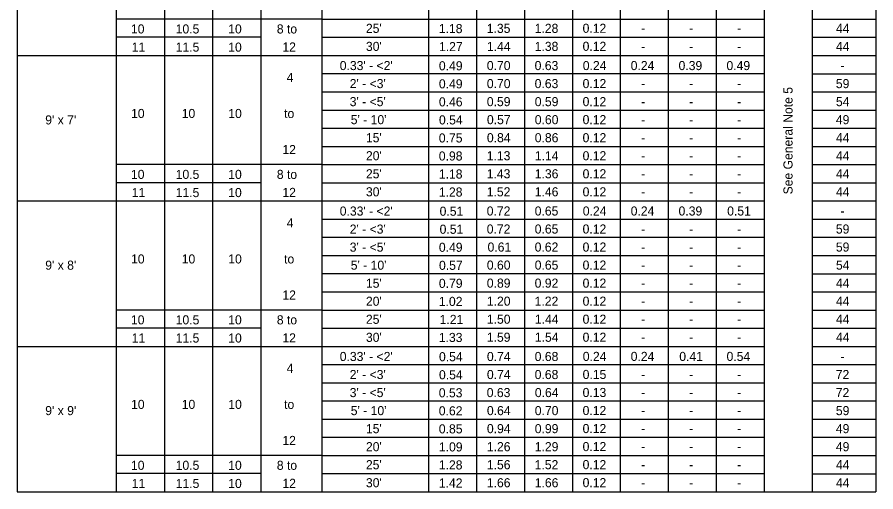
# Model space of a CAD drawing. Extents: x 10346.98 to 10349.19, y 76371.36 to 76372.62.
# Drawn here: x 10347.625 to 10348.22, y 76371.961 to 76372.289 of the extents above; entities that cross this region are included whole.
import ezdxf

# ---------------------------------------------------------------- set-up
doc = ezdxf.new("R2010")
doc.units = 0
doc.layers.add('AdhocPoint_dp', color=7, linetype='Continuous')
doc.layers.add('PlotBorder_dp', color=7, linetype='Continuous')

msp = doc.modelspace()

# ---------------------------------------------------------------- linework, layer by layer
at = {"layer": 'PlotBorder_dp'}
for p, q in [((10347.62504, 76372.53475), (10347.62504, 76371.96053)), ((10348.21977, 76372.53475), (10348.21977, 76371.96053)), ((10347.69367, 76372.51488), (10347.69367, 76371.96053)), ((10347.83612, 76372.51488), (10347.83612, 76371.96053)), ((10347.91, 76372.51488), (10347.91, 76371.96053)), ((10348.17559, 76372.51488), (10348.17559, 76371.96053)), ((10347.72703, 76372.50228), (10347.72703, 76371.96053)), ((10347.76039, 76372.50228), (10347.76039, 76371.96053)), ((10347.79375, 76372.50228), (10347.79375, 76371.96053)), ((10347.9432, 76372.47713), (10347.9432, 76371.96053)), ((10347.97639, 76372.47713), (10347.97639, 76371.96053)), ((10348.00959, 76372.47713), (10348.00959, 76371.96053)), ((10348.04279, 76372.47713), (10348.04279, 76371.96053)), ((10348.07599, 76372.47713), (10348.07599, 76371.96053)), ((10348.07599, 76372.47713), (10348.07599, 76371.96053)), ((10348.10919, 76372.47713), (10348.10919, 76371.96053)), ((10348.14239, 76372.47713), (10348.14239, 76371.96053)), ((10347.83612, 76372.28813), (10347.69367, 76372.28813)), ((10347.83612, 76372.28813), (10348.14239, 76372.28813)), ((10348.17559, 76372.28811), (10348.21977, 76372.28811)), ((10347.79375, 76372.27553), (10347.69367, 76372.27553)), ((10347.83612, 76372.27553), (10348.14239, 76372.27553)), ((10348.17559, 76372.27551), (10348.21977, 76372.27551)), ((10347.62504, 76372.26293), (10348.14239, 76372.26293)), ((10347.83673, 76372.26291), (10347.9089, 76372.26291)), ((10348.17559, 76372.26291), (10348.21977, 76372.26291)), ((10347.83612, 76372.25033), (10348.14239, 76372.25033)), ((10348.17559, 76372.25031), (10348.21977, 76372.25031)), ((10347.83612, 76372.23773), (10348.14239, 76372.23773)), ((10348.17559, 76372.23771), (10348.21977, 76372.23771)), ((10347.83612, 76372.22513), (10348.14239, 76372.22513)), ((10348.17559, 76372.22511), (10348.21977, 76372.22511)), ((10347.83612, 76372.21253), (10348.14239, 76372.21253)), ((10348.17559, 76372.21251), (10348.21977, 76372.21251)), ((10347.83612, 76372.19993), (10348.14239, 76372.19993)), ((10348.17559, 76372.19991), (10348.21977, 76372.19991)), ((10347.83612, 76372.18733), (10347.69367, 76372.18733)), ((10347.83612, 76372.18733), (10348.14239, 76372.18733)), ((10348.17559, 76372.18731), (10348.21977, 76372.18731)), ((10347.79375, 76372.17473), (10347.69367, 76372.17473)), ((10347.83612, 76372.17473), (10348.14239, 76372.17473)), ((10348.17559, 76372.17471), (10348.21977, 76372.17471)), ((10347.62504, 76372.16213), (10348.14239, 76372.16213)), ((10347.83673, 76372.16211), (10347.9089, 76372.16211)), ((10347.83673, 76372.16211), (10347.9089, 76372.16211)), ((10348.17559, 76372.16211), (10348.21977, 76372.16211)), ((10347.83612, 76372.14953), (10348.14239, 76372.14953)), ((10348.17559, 76372.14951), (10348.21977, 76372.14951)), ((10347.83612, 76372.13693), (10348.14239, 76372.13693)), ((10348.17559, 76372.13691), (10348.21977, 76372.13691)), ((10347.83612, 76372.12433), (10348.14239, 76372.12433)), ((10348.17559, 76372.12431), (10348.21977, 76372.12431)), ((10347.83612, 76372.11173), (10348.14239, 76372.11173)), ((10348.17559, 76372.11171), (10348.21977, 76372.11171)), ((10347.83612, 76372.09913), (10348.14239, 76372.09913)), ((10348.17559, 76372.09911), (10348.21977, 76372.09911)), ((10347.83612, 76372.08653), (10347.69367, 76372.08653)), ((10347.83612, 76372.08653), (10348.14239, 76372.08653)), ((10348.17559, 76372.08651), (10348.21977, 76372.08651)), ((10347.79375, 76372.07393), (10347.69367, 76372.07393)), ((10347.83612, 76372.07393), (10348.14239, 76372.07393)), ((10348.17559, 76372.07391), (10348.21977, 76372.07391)), ((10347.62504, 76372.06133), (10348.14239, 76372.06133)), ((10347.83673, 76372.06131), (10347.9089, 76372.06131)), ((10347.83673, 76372.06131), (10347.9089, 76372.06131)), ((10347.83673, 76372.06131), (10347.9089, 76372.06131)), ((10348.17559, 76372.06131), (10348.21977, 76372.06131)), ((10347.83612, 76372.04873), (10348.14239, 76372.04873)), ((10348.17559, 76372.04871), (10348.21977, 76372.04871)), ((10347.83612, 76372.03613), (10348.14239, 76372.03613)), ((10348.17559, 76372.03611), (10348.21977, 76372.03611)), ((10347.83612, 76372.02353), (10348.14239, 76372.02353)), ((10348.17559, 76372.02351), (10348.21977, 76372.02351)), ((10347.83612, 76372.01093), (10348.14239, 76372.01093)), ((10348.17559, 76372.01091), (10348.21977, 76372.01091)), ((10347.83612, 76371.99833), (10348.14239, 76371.99833)), ((10348.17559, 76371.99831), (10348.21977, 76371.99831)), ((10347.83612, 76371.98573), (10347.69367, 76371.98573)), ((10347.83612, 76371.98573), (10348.14239, 76371.98573)), ((10348.17559, 76371.98571), (10348.21977, 76371.98571)), ((10347.79375, 76371.97313), (10347.69367, 76371.97313)), ((10347.83612, 76371.97313), (10348.14239, 76371.97313)), ((10348.17559, 76371.97311), (10348.21977, 76371.97311)), ((10347.62504, 76371.96053), (10348.21977, 76371.96053))]:
    msp.add_line(p, q, dxfattribs=at)

# ---------------------------------------------------------------- texts
at = {"layer": 'AdhocPoint_dp'}
for s, p in [('10', (10347.70384, 76372.27818)), ('10.5', (10347.73483, 76372.27818)), ('10', (10347.77122, 76372.27818)), ('8 to', (10347.80488, 76372.27818)), ('11', (10347.70435, 76372.26558)), ('11.5', (10347.73483, 76372.26558)), ('10', (10347.77122, 76372.26558)), ('12', (10347.80874, 76372.26568)), ('10', (10347.70384, 76372.17738)), ('10.5', (10347.73483, 76372.17738)), ('10', (10347.77122, 76372.17738)), ('8 to', (10347.80488, 76372.17738)), ('11', (10347.70435, 76372.16478)), ('11.5', (10347.73483, 76372.16478)), ('10', (10347.77122, 76372.16478)), ('12', (10347.80874, 76372.16488)), ('10', (10347.70384, 76372.07658)), ('10.5', (10347.73483, 76372.07658)), ('10', (10347.77122, 76372.07658)), ('8 to', (10347.80488, 76372.07658)), ('11', (10347.70435, 76372.06398)), ('11.5', (10347.73483, 76372.06398)), ('10', (10347.77122, 76372.06398)), ('12', (10347.80874, 76372.06408)), ('10', (10347.70384, 76371.97578)), ('10.5', (10347.73483, 76371.97578)), ('10', (10347.77122, 76371.97578)), ('8 to', (10347.80488, 76371.97578)), ('11', (10347.70435, 76371.96318)), ('11.5', (10347.73483, 76371.96318)), ('10', (10347.77122, 76371.96318)), ('12', (10347.80874, 76371.96328))]:
    msp.add_text(s, height=0.0063, dxfattribs=at).set_placement(p)
msp.add_text('See General Note 5', height=0.0063, rotation=90, dxfattribs=at).set_placement((10348.16209, 76372.16663))
at = {"layer": 'PlotBorder_dp'}
for s, p in [("25'", (10347.8666, 76372.27858)), ('1.18', (10347.91709, 76372.27842)), ('1.35', (10347.9503, 76372.27858)), ('1.28', (10347.98349, 76372.27858)), ('0.12', (10348.01668, 76372.27863)), ('-', (10348.05726, 76372.27863)), ('-', (10348.09047, 76372.27863)), ('-', (10348.12366, 76372.27863)), ('44', (10348.19216, 76372.27858)), ("30'", (10347.8666, 76372.26608)), ('1.27', (10347.91721, 76372.26592)), ('1.44', (10347.9504, 76372.26608)), ('1.38', (10347.98349, 76372.26608)), ('0.12', (10348.01668, 76372.26613)), ('-', (10348.05726, 76372.26613)), ('-', (10348.09047, 76372.26613)), ('-', (10348.12366, 76372.26613)), ('44', (10348.19216, 76372.26608)), ("0.33' - <2'", (10347.84847, 76372.2528)), ('0.49', (10347.91714, 76372.25264)), ('0.70', (10347.95035, 76372.2528)), ('0.63', (10347.98347, 76372.2528)), ('0.24', (10348.0168, 76372.2528)), ('0.24', (10348.04999, 76372.2528)), ('0.39', (10348.08314, 76372.2528)), ('0.49', (10348.11632, 76372.2528)), ('4', (10347.8117, 76372.24458)), ('-', (10348.19536, 76372.2528)), ("2' - <3'", (10347.85537, 76372.2403)), ('0.49', (10347.91714, 76372.24014)), ('0.70', (10347.95035, 76372.2403)), ('0.63', (10347.98347, 76372.2403)), ('0.12', (10348.01668, 76372.2403)), ('59', (10348.1921, 76372.2403)), ('-', (10348.05726, 76372.2403)), ('-', (10348.09047, 76372.2403)), ('-', (10348.12366, 76372.2403)), ("3' - <5'", (10347.85537, 76372.2278)), ('0.46', (10347.91714, 76372.22764)), ('0.59', (10347.95034, 76372.2278)), ('0.59', (10347.98354, 76372.2278)), ('0.12', (10348.01668, 76372.2278)), ('54', (10348.19216, 76372.2278)), ('-', (10348.05726, 76372.2278)), ('-', (10348.09047, 76372.2278)), ('-', (10348.12366, 76372.2278)), ("9' x 7'", (10347.64447, 76372.21514)), ('10', (10347.70392, 76372.21958)), ('10', (10347.73901, 76372.21958)), ('10', (10347.77125, 76372.21958)), ('to', (10347.80992, 76372.21958)), ("5' - 10'", (10347.85608, 76372.2153)), ('0.54', (10347.9172, 76372.21514)), ('0.57', (10347.95041, 76372.2153)), ('0.60', (10347.98355, 76372.2153)), ('0.12', (10348.01668, 76372.2153)), ('49', (10348.1921, 76372.2153)), ('-', (10348.05726, 76372.2153)), ('-', (10348.09047, 76372.2153)), ('-', (10348.12366, 76372.2153)), ("15'", (10347.8666, 76372.2028)), ('0.84', (10347.9504, 76372.2028)), ('0.86', (10347.98354, 76372.2028)), ('0.12', (10348.01668, 76372.2028)), ('44', (10348.19216, 76372.2028)), ('0.75', (10347.9171, 76372.20264)), ('-', (10348.05726, 76372.2028)), ('-', (10348.09047, 76372.2028)), ('-', (10348.12366, 76372.2028)), ('12', (10347.80874, 76372.19458)), ("20'", (10347.8666, 76372.1903)), ('0.98', (10347.91709, 76372.19014)), ('1.13', (10347.95027, 76372.1903)), ('1.14', (10347.9836, 76372.1903)), ('0.12', (10348.01668, 76372.1903)), ('-', (10348.05726, 76372.1903)), ('-', (10348.09047, 76372.1903)), ('-', (10348.12366, 76372.1903)), ('44', (10348.19216, 76372.1903)), ("25'", (10347.8666, 76372.1778)), ('1.18', (10347.91709, 76372.17764)), ('1.43', (10347.95027, 76372.1778)), ('1.36', (10347.98354, 76372.1778)), ('0.12', (10348.01668, 76372.1778)), ('-', (10348.05726, 76372.1778)), ('-', (10348.09047, 76372.1778)), ('-', (10348.12366, 76372.1778)), ('44', (10348.19216, 76372.1778)), ("30'", (10347.8666, 76372.1653)), ('1.28', (10347.91709, 76372.16514)), ('1.52', (10347.95027, 76372.1653)), ('1.46', (10347.98354, 76372.1653)), ('0.12', (10348.01668, 76372.1653)), ('-', (10348.05726, 76372.1653)), ('-', (10348.09047, 76372.1653)), ('-', (10348.12366, 76372.1653)), ('44', (10348.19216, 76372.1653)), ("0.33' - <2'", (10347.84847, 76372.15196)), ('0.51', (10347.91764, 76372.15186)), ('0.72', (10347.95027, 76372.15202)), ('0.65', (10347.9835, 76372.15202)), ('0.24', (10348.0168, 76372.15202)), ('0.24', (10348.04999, 76372.15202)), ('0.39', (10348.08314, 76372.15202)), ('0.51', (10348.11682, 76372.15202)), ('4', (10347.8117, 76372.14378)), ('-', (10348.19536, 76372.15202)), ("2' - <3'", (10347.85537, 76372.13946)), ('0.51', (10347.91764, 76372.13936)), ('0.72', (10347.95027, 76372.13952)), ('0.65', (10347.9835, 76372.13952)), ('0.12', (10348.01668, 76372.13952)), ('59', (10348.1921, 76372.13952)), ('-', (10348.05726, 76372.13952)), ('-', (10348.09047, 76372.13952)), ('-', (10348.12366, 76372.13952)), ("3' - <5'", (10347.85537, 76372.12696)), ('0.49', (10347.91714, 76372.12686)), ('0.61', (10347.95084, 76372.12702)), ('0.62', (10347.98347, 76372.12702)), ('0.12', (10348.01668, 76372.12702)), ('59', (10348.1921, 76372.12702)), ('-', (10348.05726, 76372.12702)), ('-', (10348.09047, 76372.12702)), ('-', (10348.12366, 76372.12702)), ("9' x 8'", (10347.64447, 76372.11446)), ('10', (10347.70392, 76372.11878)), ('10', (10347.73901, 76372.11878)), ('10', (10347.77125, 76372.11878)), ('to', (10347.80992, 76372.11878)), ("5' - 10'", (10347.85608, 76372.11446)), ('0.57', (10347.91721, 76372.11436)), ('0.60', (10347.95035, 76372.11452)), ('0.65', (10347.9835, 76372.11452)), ('0.12', (10348.01668, 76372.11452)), ('54', (10348.19216, 76372.11452)), ('-', (10348.05726, 76372.11452)), ('-', (10348.09047, 76372.11452)), ('-', (10348.12366, 76372.11452)), ("15'", (10347.8666, 76372.10196)), ('0.79', (10347.91714, 76372.10186)), ('0.89', (10347.95034, 76372.10202)), ('0.92', (10347.98347, 76372.10202)), ('0.12', (10348.01668, 76372.10202)), ('44', (10348.19216, 76372.10202)), ('-', (10348.05726, 76372.10202)), ('-', (10348.09047, 76372.10202)), ('-', (10348.12366, 76372.10202)), ('12', (10347.80874, 76372.09378)), ("20'", (10347.8666, 76372.08946)), ('1.02', (10347.91707, 76372.08936)), ('1.20', (10347.95035, 76372.08952)), ('1.22', (10347.98347, 76372.08952)), ('0.12', (10348.01668, 76372.08952)), ('-', (10348.05726, 76372.08952)), ('-', (10348.09047, 76372.08952)), ('-', (10348.12366, 76372.08952)), ('44', (10348.19216, 76372.08952)), ("25'", (10347.8666, 76372.07696)), ('1.21', (10347.91764, 76372.07686)), ('1.50', (10347.95035, 76372.07702)), ('1.44', (10347.9836, 76372.07702)), ('0.12', (10348.01668, 76372.07702)), ('-', (10348.05726, 76372.07702)), ('-', (10348.09047, 76372.07702)), ('-', (10348.12366, 76372.07702)), ('44', (10348.19216, 76372.07702)), ("30'", (10347.8666, 76372.06446)), ('1.33', (10347.91707, 76372.06436)), ('1.59', (10347.95034, 76372.06452)), ('1.54', (10347.9836, 76372.06452)), ('0.12', (10348.01668, 76372.06452)), ('-', (10348.05726, 76372.06452)), ('-', (10348.09047, 76372.06452)), ('-', (10348.12366, 76372.06452)), ('44', (10348.19216, 76372.06452)), ("0.33' - <2'", (10347.84847, 76372.05118)), ('0.54', (10347.9172, 76372.05103)), ('0.74', (10347.9504, 76372.05118)), ('0.68', (10347.98349, 76372.05118)), ('0.24', (10348.0168, 76372.05124)), ('0.24', (10348.04999, 76372.05124)), ('0.41', (10348.08364, 76372.05124)), ('0.54', (10348.11638, 76372.05124)), ('4', (10347.8117, 76372.04298)), ('-', (10348.19536, 76372.05118)), ("2' - <3'", (10347.85537, 76372.03868)), ('0.54', (10347.9172, 76372.03853)), ('0.74', (10347.9504, 76372.03868)), ('0.68', (10347.98349, 76372.03868)), ('0.15', (10348.01671, 76372.03874)), ('72', (10348.19203, 76372.03868)), ('-', (10348.05726, 76372.03874)), ('-', (10348.09047, 76372.03874)), ('-', (10348.12366, 76372.03874)), ("3' - <5'", (10347.85537, 76372.02618)), ('0.53', (10347.91707, 76372.02603)), ('0.63', (10347.95027, 76372.02618)), ('0.64', (10347.9836, 76372.02618)), ('0.13', (10348.01668, 76372.02624)), ('72', (10348.19203, 76372.02618)), ('-', (10348.05726, 76372.02624)), ('-', (10348.09047, 76372.02624)), ('-', (10348.12366, 76372.02624)), ("9' x 9'", (10347.64447, 76372.01368)), ('10', (10347.70392, 76372.01798)), ('10', (10347.73901, 76372.01798)), ('10', (10347.77125, 76372.01798)), ('to', (10347.80992, 76372.01798)), ("5' - 10'", (10347.85608, 76372.01368)), ('0.62', (10347.91707, 76372.01353)), ('0.64', (10347.9504, 76372.01368)), ('0.70', (10347.98355, 76372.01368)), ('0.12', (10348.01668, 76372.01374)), ('59', (10348.1921, 76372.01368)), ('-', (10348.05726, 76372.01374)), ('-', (10348.09047, 76372.01374)), ('-', (10348.12366, 76372.01374)), ("15'", (10347.8666, 76372.00118)), ('0.85', (10347.9171, 76372.00103)), ('0.94', (10347.9504, 76372.00118)), ('0.99', (10347.98354, 76372.00118)), ('0.12', (10348.01668, 76372.00124)), ('49', (10348.1921, 76372.00118)), ('-', (10348.05726, 76372.00124)), ('-', (10348.09047, 76372.00124)), ('-', (10348.12366, 76372.00124)), ('12', (10347.80874, 76371.99298)), ("20'", (10347.8666, 76371.98868)), ('1.26', (10347.95034, 76371.98868)), ('1.29', (10347.98354, 76371.98868)), ('0.12', (10348.01668, 76371.98874)), ('49', (10348.1921, 76371.98868)), ('1.09', (10347.91714, 76371.98853)), ('-', (10348.05726, 76371.98874)), ('-', (10348.09047, 76371.98874)), ('-', (10348.12366, 76371.98874)), ("25'", (10347.8666, 76371.97618)), ('1.28', (10347.91709, 76371.97603)), ('1.56', (10347.95034, 76371.97618)), ('1.52', (10347.98347, 76371.97618)), ('0.12', (10348.01668, 76371.97624)), ('-', (10348.05726, 76371.97624)), ('-', (10348.09047, 76371.97624)), ('-', (10348.12366, 76371.97624)), ('44', (10348.19216, 76371.97618)), ("30'", (10347.8666, 76371.96368)), ('1.42', (10347.91707, 76371.96353)), ('1.66', (10347.95034, 76371.96368)), ('1.66', (10347.98354, 76371.96368)), ('0.12', (10348.01668, 76371.96374)), ('-', (10348.05726, 76371.96374)), ('-', (10348.09047, 76371.96374)), ('-', (10348.12366, 76371.96374)), ('44', (10348.19216, 76371.96368))]:
    msp.add_text(s, height=0.0063, dxfattribs=at).set_placement(p)

doc.saveas('drawing.dxf')
